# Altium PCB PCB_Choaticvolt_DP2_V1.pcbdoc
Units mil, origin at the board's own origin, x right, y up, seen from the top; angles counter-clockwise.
Board outline 3255.91 x 2971.14 mil, 2 copper layers (Top Layer, Bottom Layer); 27 components, 42 nets, 120 pads, 50 vias.
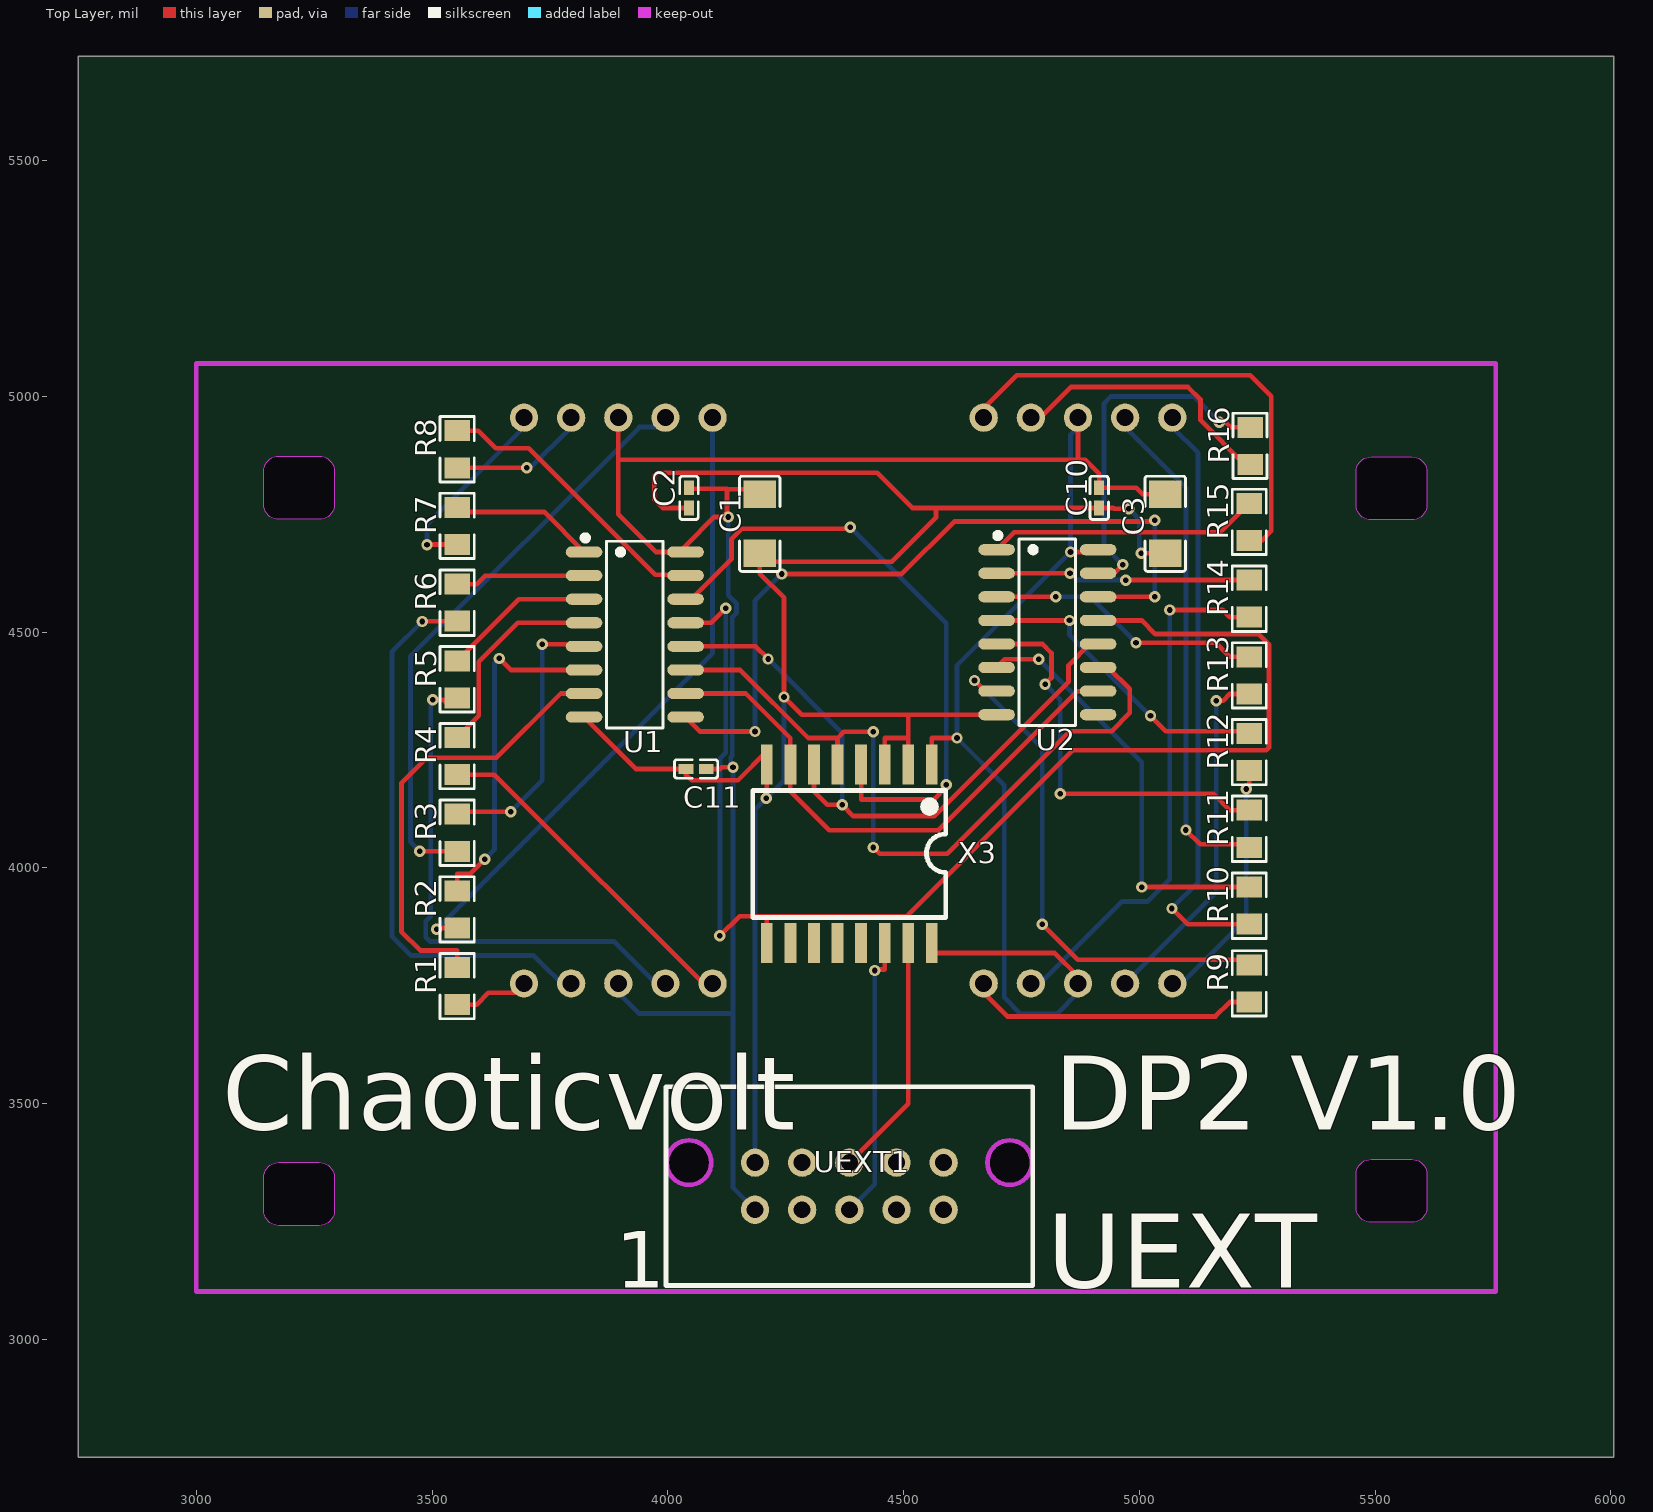
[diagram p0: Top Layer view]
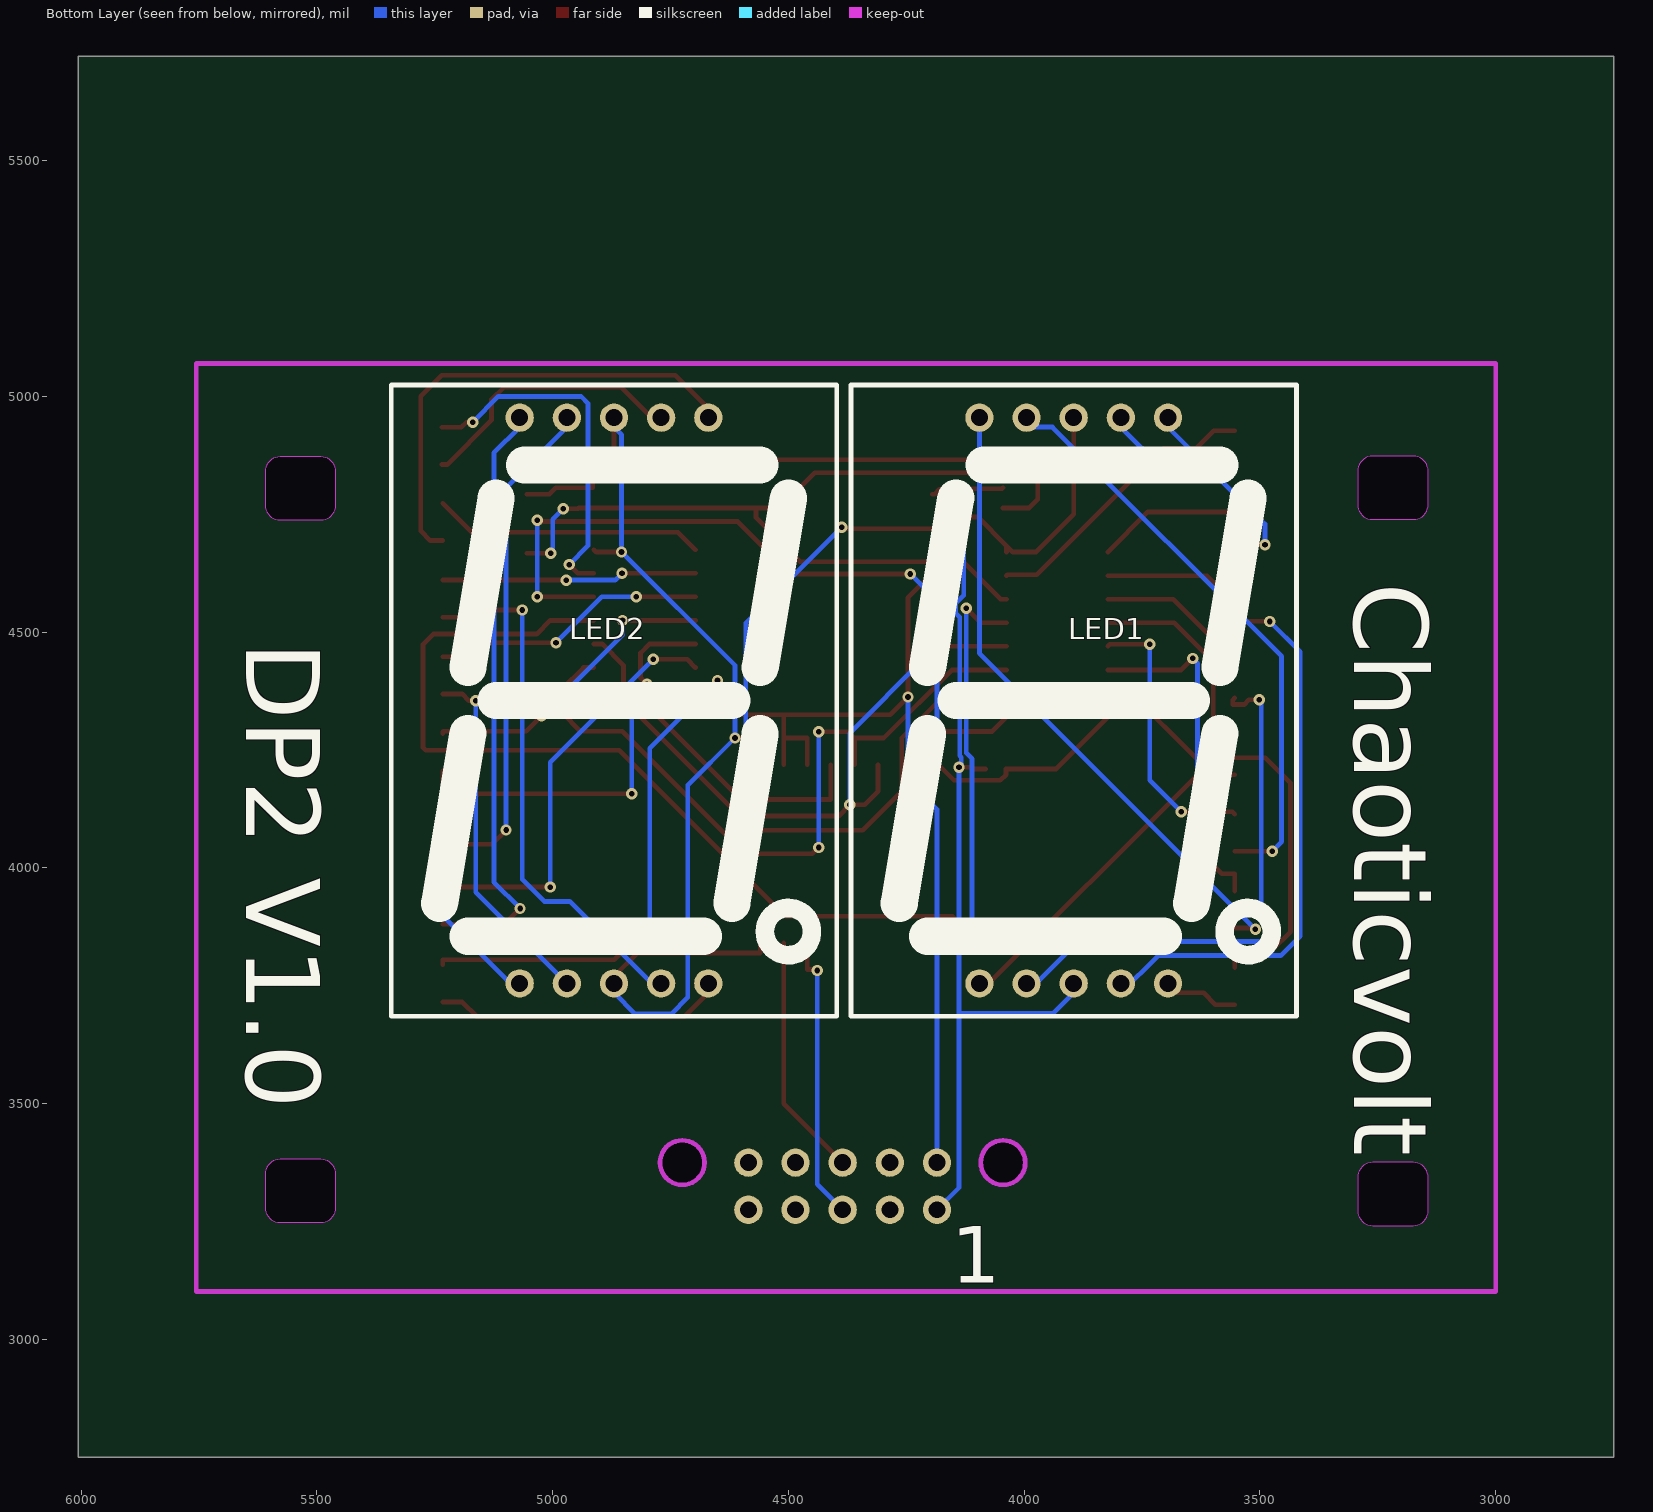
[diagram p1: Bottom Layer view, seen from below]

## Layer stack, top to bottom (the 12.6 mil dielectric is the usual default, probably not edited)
Top Layer: signal copper (thickness not stored)
Dielectric: dielectric 12.6, FR-4, Dk 4.8
Bottom Layer: signal copper (thickness not stored)

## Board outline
6005.91,2750 2750,2750 2750,5721.14 6005.91,5721.14
cut-out: 3174.61,4873.15 3261.22,4873.15 cw(c3261.22,4841.65) 3292.72,4841.65 3292.72,4770.79 cw(c3261.22,4770.79) 3261.22,4739.29 3174.61,4739.29 cw(c3174.61,4770.79) 3143.11,4770.79 3143.11,4841.65 cw(c3174.61,4841.65)
cut-out: 3174.61,3375.28 3261.22,3375.28 cw(c3261.22,3343.78) 3292.72,3343.78 3292.72,3272.91 cw(c3261.22,3272.91) 3261.22,3241.42 3174.61,3241.42 cw(c3174.61,3272.91) 3143.11,3272.91 3143.11,3343.78 cw(c3174.61,3343.78)
cut-out: 5491.69,3381.93 5578.31,3381.93 cw(c5578.31,3350.43) 5609.8,3350.43 5609.8,3279.57 cw(c5578.31,3279.57) 5578.31,3248.07 5491.69,3248.07 cw(c5491.69,3279.57) 5460.2,3279.57 5460.2,3350.43 cw(c5491.69,3350.43)
cut-out: 5491.69,4871.93 5578.31,4871.93 cw(c5578.31,4840.43) 5609.8,4840.43 5609.8,4769.57 cw(c5578.31,4769.57) 5578.31,4738.07 5491.69,4738.07 cw(c5491.69,4769.57) 5460.2,4769.57 5460.2,4840.43 cw(c5491.69,4840.43)

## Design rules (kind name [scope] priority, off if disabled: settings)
Clearance copperThickness1oz [All] p1: gap=7 ignorepadtopadclearanceinfootprint=FALSE except(4: Track-Track; 6: Track-SMDPad SMDPad-SMDPad Track-THPad SMDPad-THPad THPad-THPad Track-Via SMDPad-Via THPad-Via Via-Via SMDPad-Fill THPad-Fill Via-Fill Fill-Fill Track-Region SMDPad-Region THPad-Region Via-Region Region-Region Track-Poly SMDPad-Poly THPad-Poly Via-Poly Fill-Poly Region-Poly Poly-Poly Track-Text SMDPad-Text THPad-Text Via-Text Fill-Text Region-Text Poly-Text Text-Text; 6.9: Track-Hole SMDPad-Hole THPad-Hole Via-Hole Fill-Hole Region-Hole Poly-Hole Text-Hole Sheet-Hole; 11.8: Track-Fill Fill-Region Track-Sheet SMDPad-Sheet THPad-Sheet Via-Sheet Fill-Sheet Region-Sheet Poly-Sheet Text-Sheet)
Clearance copperThickness2oz [All] p1: gap=7 ignorepadtopadclearanceinfootprint=FALSE except(6: Track-SMDPad SMDPad-SMDPad Track-THPad SMDPad-THPad THPad-THPad Track-Via SMDPad-Via THPad-Via Via-Via SMDPad-Fill THPad-Fill Via-Fill Fill-Fill Track-Region SMDPad-Region THPad-Region Via-Region Region-Region Track-Poly SMDPad-Poly THPad-Poly Via-Poly Fill-Poly Region-Poly Poly-Poly Track-Text SMDPad-Text THPad-Text Via-Text Fill-Text Region-Text Poly-Text Text-Text; 6.9: Track-Hole SMDPad-Hole THPad-Hole Via-Hole Fill-Hole Region-Hole Poly-Hole Text-Hole Sheet-Hole; 8: Track-Track; 11.8: Track-Fill Fill-Region Track-Sheet SMDPad-Sheet THPad-Sheet Via-Sheet Fill-Sheet Region-Sheet Poly-Sheet Text-Sheet)
DiffPairsRouting differentialPair [All] p1: maxuncoupledlength=10 maxlimit=5.9843 mostfreqgap=5.9843 toplayer_minwidth=5 toplayer_prefwidth=10 toplayer_maxwidth=100 bottomlayer_minwidth=5 bottomlayer_prefwidth=10 bottomlayer_maxwidth=100
PasteMaskExpansion pasteMaskExpansion [All] p1:
PlaneConnect innerPlane [All] p1: planeconnectstyle=Relief reliefexpansion=20 reliefentries=4 reliefconductorwidth=10 reliefairgap=10
PolygonConnect copperRegion [All] p1: connectstyle=Relief reliefentries=4 reliefconductorwidth=10 polygonreliefangle="90 Angle" airgapwidth=10
PolygonConnect CV-CopperRule01 [All] p1: connectstyle=Relief reliefentries=4 reliefconductorwidth=10 polygonreliefangle="45 Angle" airgapwidth=10
RoutingVias viaSize [All] p1: viastyle="Through Hole" holewidth=12.0078 minholewidth=11.811 maxholewidth=248.0314 width=24.0158 minwidth=19.685 maxwidth=393.7008
SolderMaskExpansion solderMaskExpansion [All] p1: useseparateexpansions=TRUE expansion=2.0079 expansionbottom=2.0079
Width copperThickness1oz [All] p1: maxlimit=100 minlimit=5 preferedwidth=10
Width copperThickness2oz [All] p1: maxlimit=100 minlimit=8 preferedwidth=10

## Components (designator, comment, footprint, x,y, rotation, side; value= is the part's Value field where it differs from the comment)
C1 "CL31A476MPHNNNE" C1206 4195,4730 r270 top
C2 "CL05B104KO5NNNC" C0402 4045,4784.92 r270 top
C3 "CL31A476MPHNNNE" C1206 5055,4730 r270 top
C10 "CL05B104KO5NNNC" C0402 4915,4784.92 r270 top
C11 "CL05B104KO5NNNC" C0402 4060,4210 r0 top
LED1 "SM411006N/15" LED-SEG-TH_10P-L24.0-W34.0-P2.54-S30.48-BL 3895,4355 r180 bottom
LED2 "SM411006N/15" LED-SEG-TH_10P-L24.0-W34.0-P2.54-S30.48-BL 4870,4355 r180 bottom
R1 "0805W8F1200T5E" R0805 3553.23,3749.29 r90 top
R2 "0805W8F1200T5E" R0805 3553.23,3911.97 r90 top
R3 "0805W8F1200T5E" R0805 3553.23,4074.64 r90 top
R4 "0805W8F1200T5E" R0805 3553.23,4237.31 r90 top
R5 "0805W8F1200T5E" R0805 3553.23,4399.98 r90 top
R6 "0805W8F1200T5E" R0805 3553.23,4562.65 r90 top
R7 "0805W8F1200T5E" R0805 3553.23,4725.33 r90 top
R8 "0805W8F1200T5E" R0805 3553.23,4888 r90 top
R9 "0805W8F1200T5E" R0805 5233.29,3755 r90 top
R10 "0805W8F1200T5E" R0805 5233.29,3920 r90 top
R11 "0805W8F1200T5E" R0805 5233.29,4083.1 r90 top
R12 "0805W8F1200T5E" R0805 5233.29,4245.77 r90 top
R13 "0805W8F1200T5E" R0805 5233.29,4408.44 r90 top
R14 "0805W8F1200T5E" R0805 5233.29,4571.11 r90 top
R15 "0805W8F1200T5E" R0805 5233.29,4733.79 r90 top
R16 "0805W8F1200T5E" R0805 5235,4895 r90 top
U1 "74HC595D,118" SOIC-16_L9.9-W3.9-P1.27-LS6.0-BL 3930,4495 r270 top
U2 "74HC595D,118" SOIC-16_L9.9-W3.9-P1.27-LS6.0-BL 4805,4500 r270 top
UEXT1 "15477610" IDC-TH_15477610 4385,3325 r0 top
X3 "PCF8574T/TR" SO-16_L10.3-W7.5-P1.27-LS10.3-BL 4385,4030 r180 top

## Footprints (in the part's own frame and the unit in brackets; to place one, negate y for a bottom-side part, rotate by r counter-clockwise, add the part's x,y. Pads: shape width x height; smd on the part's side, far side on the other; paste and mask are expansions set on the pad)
C0402 [mm]
  rect 0.79x0.54 smd: 1(-0.545,0) 2(0.545,0)
  silkscreen extent -1.17,-0.5 1.17,0.5
C1206 [mm]
  rect 1.485x1.728 smd: 1(-1.593,0) 2(1.593,0)
  silkscreen extent -2.56,-1.09 2.56,1.09
IDC-TH_15477610 [mil]
  round 60 hole 36: 1(-200,-50) 2(-200,50) 3(-100,-50) 4(-100,50) 5(0,-50) 6(0,50) 7(100,-50) 8(100,50) 9(200,-50) 10(200,50)
  Multi-Layer board cut-out: -292.92,50 -299.39,73.44 -316.66,90.55 -340.16,96.81 -363.65,90.55 -380.93,73.44 -387.4,50 -387.4,50 -380.93,26.56 -363.65,9.45 -340.16,3.19 -316.66,9.45 -299.39,26.56 -292.92,50
  Multi-Layer board cut-out: 387.4,50 380.93,73.44 363.66,90.55 340.16,96.81 316.67,90.55 299.39,73.44 292.92,50 292.92,50 299.39,26.56 316.67,9.45 340.16,3.19 363.66,9.45 380.93,26.56 387.4,50
  Multi-Layer keep-out circle w10: c-340.16,50 r47.24
  Multi-Layer keep-out circle w10: c340.16,50 r47.24
  silkscreen extent -389,-211 389,211
LED-SEG-TH_10P-L24.0-W34.0-P2.54-S30.48-BL [mil]
  round 60 hole 36: 1(-200,-600) 2(-100,-600) 3(0,-600) 4(100,-600) 5(200,-600) 6(200,600) 7(100,600) 8(0,600) 9(-100,600) 10(-200,600)
  silkscreen extent -472,-669 472,669
R0805 [mm]
  rect 1.133x1.377 smd: 1(-1,0) 2(1,0)
  silkscreen extent -1.76,-0.92 1.76,0.92
SO-16_L10.3-W7.5-P1.27-LS10.3-BL [mm]
  rect 0.635x2.16 smd: 1(-4.445,-4.8) 2(-3.175,-4.8) 3(-1.905,-4.8) 4(-0.635,-4.8) 5(0.635,-4.8) 6(1.905,-4.8) 7(3.175,-4.8) 8(4.445,-4.8) 9(4.445,4.8) 10(3.175,4.8) 11(1.905,4.8) 12(0.635,4.8) 13(-0.635,4.8) 14(-1.905,4.8) 15(-3.175,4.8) 16(-4.445,4.8)
  silkscreen extent -5.19,-3.41 5.21,3.43
SOIC-16_L9.9-W3.9-P1.27-LS6.0-BL [mil]
  oval 23.7x77.6 smd: 1(-175,-107.7) 2(-125,-107.7) 3(-75,-107.7) 4(-25,-107.7) 5(25,-107.7) 6(75,-107.7) 7(125,-107.7) 8(175,-107.7) 9(175,107.7) 10(125,107.7) 11(75,107.7) 12(25,107.7) 13(-25,107.7) 14(-75,107.7) 15(-125,107.7) 16(-175,107.7)
  silkscreen extent -211,-111 198,60

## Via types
v1: diameter 24, hole 12, Top Layer to Bottom Layer, 50 vias

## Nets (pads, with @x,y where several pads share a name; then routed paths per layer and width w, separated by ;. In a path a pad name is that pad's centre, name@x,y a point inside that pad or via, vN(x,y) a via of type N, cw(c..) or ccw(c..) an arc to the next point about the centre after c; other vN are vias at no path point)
$1N2392: R1.2 U1.7 | length 952.1
  Top Layer w10: R1.2 3553.2,3825.1 3474.97,3825.1 3435,3864.96 3435,4180 3488.8,4233.8 3636.5,4233.8 3772.7,4370 U1.7
$1N2394: R4.2 U1.4 | length 436.9
  Top Layer w10: R4.2 3599,4322.5 3599,4436.9 3682,4520 U1.4
$1N2395: R6.2 U1.2 | length 276.6
  Top Layer w10: R6.2 3594.4,4602 3612.4,4620 U1.2
$1N2396: R7.2 U1.1 | length 314
  Top Layer w10: R7.2 3553.2,4755 3737.44,4755 U1.1
$1N2397: R2.2 U1.6 | length 736.5
  Top Layer w10: R2.2 3553.2,3987.7 3581.1,3987.7 v1(3611.7,4018.3) ; v1(3642.2,4444.4) 3666.6,4420 U1.6
  Bottom Layer w10: v1(3611.7,4018.3) 3632.2,4038.8 3632.2,4434.4 v1(3642.2,4444.4)
$1N2398: R5.2 U1.3 | length 329.4
  Top Layer w10: R5.2 3553.2,4450 3563.8,4450 3683.8,4570 U1.3
$1N2399: R3.2 U1.5 | length 589.3
  Top Layer w10: R3.2 3558.2,4119 v1(3667,4119) ; v1(3733.8,4474.4) 3818,4474.4 U1.5
  Bottom Layer w10: v1(3667,4119) 3733.8,4185.8 v1(3733.8,4474.4)
$1N2400: R8.2 U1.15 | length 611.8
  Top Layer w10: R8.2 3597.6,4927.4 3635,4890 3705,4890 3973.3,4621.7 4036,4621.7 U1.15
$1N2411: R9.2 U2.7 | length 1113.8
  Top Layer w10: v1(4650.5,4397.7) 4673.2,4375 U2.7 ; v1(4794.1,3880.8) 4869.9,3805 5233.3,3805 R9.2
  Bottom Layer w10: v1(4650.5,4397.7) 4794.1,4254.1 v1(4794.1,3880.8)
$1N2412: R12.2 U2.4 | length 655.5
  Top Layer w10: U2.4 v1(4851.9,4525) ; v1(5023.7,4322.6) 5056.3,4290 5232.2,4290 5233.3,4288.9 R12.2
  Bottom Layer w10: v1(4851.9,4525) 4851.9,4494.4 v1(5023.7,4322.6)
$1N2413: R14.2 U2.2 | length 542
  Top Layer w10: U2.2 v1(4852.9,4625) ; v1(4971.5,4610.5) R14.2
  Bottom Layer w10: v1(4852.9,4625) 4867.4,4610.5 v1(4971.5,4610.5)
$1N2414: R15.2 U2.1 | length 576.7
  Top Layer w10: U2.1 4734.4,4712.1 5172.2,4712.1 R15.2
$1N2415: R10.2 U2.6 | length 898.6
  Top Layer w10: U2.6 4715.1,4442.8 v1(4786.6,4442.8) ; v1(5005.4,3959.4) R10.2
  Bottom Layer w10: v1(4786.6,4442.8) 5005.4,4224.1 v1(5005.4,3959.4)
$1N2416: R13.2 U2.3 | length 588.7
  Top Layer w10: U2.3 v1(4822.6,4575) ; v1(4993.1,4477.7) 5162.3,4477.7 5192.2,4447.8 R13.2
  Bottom Layer w10: v1(4822.6,4575) 4895.8,4575 v1(4993.1,4477.7)
$1N2417: R11.2 U2.5 | length 857.2
  Top Layer w10: U2.5 4794.6,4475 4813.7,4455.9 4813.7,4402.9 v1(4800.2,4389.4) ; v1(4832.4,4157.3) 5157.4,4157.3 5192.2,4122.5 R11.2
  Bottom Layer w10: v1(4800.2,4389.4) 4832.4,4357.2 v1(4832.4,4157.3)
$1N2418: R16.2 U2.15 | length 761.4
  Top Layer w10: U2.15 4946.7,4625 v1(4965.1,4643.4) ; v1(5169.9,4945.3) 5182.9,4945.3 5193.9,4934.4 R16.2
  Bottom Layer w10: v1(4965.1,4643.4) 4925.2,4683.3 4925.2,4985.2 4940,5000 5115.2,5000 v1(5169.9,4945.3)
$1N2428: U1.9 U2.14 | length 1638
  Top Layer w10: U1.9 4068.2,4289.5 v1(4184.9,4289.5) ; v1(4241.9,4623.6) 4496.3,4623.6 4607.3,4734.6 5029.6,4734.6 v1(5032.6,4737.6) ; U2.14 v1(5032.6,4575)
  Bottom Layer w10: v1(4184.9,4289.5) 4184.9,4566.6 v1(4241.9,4623.6) ; v1(5032.6,4575) v1(5032.6,4737.6)
$1N2430: U1.11 U2.11 X3.5 | length 1575.8
  Top Layer w10: U1.11 4153.1,4420 4297.6,4275.6 4360,4275.6 ; X3.5 4360,4275.6 ; v1(4435.9,4043.4) 4449.3,4030 4592.49,4030 4852.6,4290 4941.3,4290 4980,4328.7 4980,4379.6 4934.6,4425 U2.11 ; v1(4435.9,4288.8) 4373.2,4288.8 4360,4275.6
  Bottom Layer w10: v1(4435.9,4043.4) v1(4435.9,4288.8)
$1N2434: U1.12 U2.12 X3.6 | length 1413.2
  Top Layer w10: U1.12 4185.9,4470 v1(4212.7,4443.2) ; X3.6 4310,4162.5 4338.6,4133.8 v1(4370,4133.8) 4393.8,4110 4565,4110 4850,4395 4850,4429.8 4895.2,4475 U2.12
  Bottom Layer w10: v1(4212.7,4443.2) 4370,4285.8 v1(4370,4133.8)
$1N2437: U1.13 U2.13 X3.9 | length 2786.4
  Top Layer w10: U1.13 4092.2,4520 v1(4122.8,4550.6) ; v1(4110.5,3855.9) 4152.2,3897.6 4210,3897.6 ; X3.9 4210,3897.6 ; U2.13 5005,4525 5033.9,4496.1 5253.1,4496.1 5275,4474.3 5275,4255.2 5269.3,4249.5 4858.8,4249.5 4506.8,3897.6 4210,3897.6
  Bottom Layer w10: v1(4110.5,3855.9) 4110.5,4231.8 4122.8,4244 v1(4122.8,4550.6)
$1N3740: U1.14 X3.4 | length 1338.3
  Top Layer w10: U1.14 4050.2,4570 4135,4654.88 4135,4697 4157.2,4719.2 4384,4719.2 v1(4387.3,4722.5) ; X3.4 4410,4145 4563.7,4145 4590.9,4172.2 v1(4590.9,4176.3)
  Bottom Layer w10: v1(4387.3,4722.5) 4590.42,4519.38 4590.42,4176.78 v1(4590.9,4176.3)
$1N3774: U1.10 U2.10 X3.7 | length 1183.6
  Top Layer w10: U1.10 4165.6,4370 4260,4275.6 X3.7 4260,4162.5 4342.34,4080 4573.7,4080 4868.7,4375 U2.10
$1N3917: UEXT1.5 X3.14 | length 608.3
  Top Layer w10: v1(4438.9,3782.5) 4440.8,3784.5 4460,3784.5 X3.14
  Bottom Layer w10: UEXT1.5 4438.9,3328.9 v1(4438.9,3782.5)
$1N3924: UEXT1.6 X3.15 | length 517.8
  Top Layer w10: UEXT1.6 4510,3500 X3.15
$1N26641: LED1.6 R7.1 | length 398.2
  Top Layer w10: v1(3489.4,4685.8) 3511.9,4685.8 3512.1,4686 R7.1
  Bottom Layer w10: v1(3489.4,4685.8) 3489.4,4729.4 LED1.6@3695,4935
$1N26647: LED1.7 R8.1 | length 277.6
  Top Layer w10: R8.1 v1(3700.7,4848.6)
  Bottom Layer w10: v1(3700.7,4848.6) 3708.6,4848.6 LED1.7@3795,4935
$1N26729: LED1.2 R5.1 | length 1143.4
  Top Layer w10: v1(3501.5,4356.5) 3523.66,4356.5 3533.66,4346.5 3557.63,4346.5 3557.63,4356.16 R5.1
  Bottom Layer w10: v1(3501.5,4356.5) 3497.18,4352.18 3497.18,3897.55 3486.62,3887.01 3486.62,3852.5 3494.92,3844.2 3885.8,3844.2 LED1.2@3995,3735
$1N26736: LED1.1 R4.1 | length 733.5
  Top Layer w10: R4.1 3632.1,4197.9 LED1.1@4095,3735
$1N26743: LED1.9 R3.1 | length 1243.2
  Top Layer w10: v1(3474.2,4035.3) R3.1
  Bottom Layer w10: v1(3474.2,4035.3) 3454.2,4055.3 3454.2,4449.2 3940,4935 LED1.9@3995,4935
$1N26751: LED1.10 R2.1 | length 1351.8
  Top Layer w10: v1(3509.6,3870.2) 3512.1,3872.6 R2.1
  Bottom Layer w10: v1(3509.6,3870.2) 4095,4455.6 LED1.10@4095,4935
$1N26868: LED2.6 R15.1 | length 1038.1
  Top Layer w10: LED2.6@4670,4935 4670,4975 4740.2,5045.2 5235.2,5045.2 5279.8,5000.7 5279.8,4714.8 5259.41,4694.41 R15.1
$1N26872: LED2.7 R16.1 | length 594
  Top Layer w10: LED2.7@4770,4935 4855,5020 5103.35,5020 5130,4993.35 5130,4949.5 5223.9,4855.6 R16.1
$1N26877: LED2.2 R13.1 | length 775.8
  Top Layer w10: v1(5163.3,4354.9) 5178,4354.9 5192.2,4369.1 R13.1
  Bottom Layer w10: LED2.2@4970,3735 LED2.2 5163.3,3948.3 v1(5163.3,4354.9)
$1N26881: LED2.1 R12.1 | length 541.1
  Top Layer w10: v1(5226.9,4167.3) 5229.7,4170.1 5233.3,4170.1 R12.1
  Bottom Layer w10: LED2.1@5070,3735 5226.9,3891.9 v1(5226.9,4167.3)
$1N26885: LED2.9 R11.1 | length 1061.3
  Top Layer w10: v1(5098.9,4080.4) 5129.3,4050 5233.3,4050 R11.1
  Bottom Layer w10: LED2.9@4970,4935 5098.9,4806.1 v1(5098.9,4080.4)
$1N26891: LED2.10 R10.1 | length 1244.5
  Top Layer w10: v1(5069.2,3914) 5102.6,3880.6 R10.1
  Bottom Layer w10: v1(5069.2,3914) 5124.6,3969.4 5124.6,4880.4 LED2.10@5070,4935
$1N27647: LED1.4 R6.1 | length 1198.4
  Top Layer w10: v1(3478.9,4522.7) 3479.5,4523.3 R6.1
  Bottom Layer w10: v1(3478.9,4522.7) 3415,4458.8 3415,3855 3455.8,3814.2 3715.8,3814.2 LED1.4@3795,3735
$1N27662: LED1.5 R1.1 | length 152.2
  Top Layer w10: R1.1 3594.4,3709.9 3619.5,3735 LED1.5@3695,3735
$1N27688: LED2.4 R14.1 | length 1140.9
  Top Layer w10: v1(5064.4,4547.2) 5176.7,4547.2 5192.2,4531.7 R14.1
  Bottom Layer w10: LED2.4@4770,3735 4964,3929 5017.7,3929 5064.4,3975.7 v1(5064.4,4547.2)
$1N27703: LED2.5 R9.1 | length 596.7
  Top Layer w10: LED2.5@4670,3735 4720,3685 5161.6,3685 5192.2,3715.6 R9.1
GND: 
VCC: C1.1 C2.1 C3.1 C10.1 C11.2 LED1.3 LED1.8 LED2.3 LED2.8 U1.16 U2.16 UEXT1.1 X3.1 X3.16 | length 5918.4
  Top Layer w10: LED1.8@3895,4935 3895,4865.7 ; U1.16 4037.7,4683.4 ; C2.1 4046.4,4805 4125.55,4803.64 ; C11.2 4111.2,4210 4114.4,4213.3 v1(4138.3,4213.3) ; v1(4127.98,4744.5) 4115.2,4744.5 ; C1.1 4190,4792.7 4180,4802.7 4125.55,4803.64 ; X3.16 4560,3819.5 4820.6,3819.5 4870.04,3769.96 LED2.3@4870,3735 ; X3.1 4560,4275.6 v1(4613.4,4275.6) ; v1(4854,4670) 4907.7,4670 U2.16 ; LED2.8@4870,4935 4870,4865.7 ; C3.1 5007,4792.7 4993.3,4806.4 C10.1 4915,4836.1 4885.4,4865.7 4870,4865.7 ; 3895,4865.7 4870,4865.7 ; 3895,4865.7 3895,4750 3975,4670 4024.3,4670 4037.7,4683.4 ; 4037.7,4683.4 4098.7,4744.5 4115.2,4744.5 ; 4115.2,4744.5 4125.55,4754.85 4125.55,4803.64
  Bottom Layer w10: LED1.3@3895,3735 3938.7,3691.3 4138.3,3691.3 ; v1(4127.98,4744.5) 4127.98,4577.92 4145.78,4560.12 4145.78,4541.08 4136.82,4532.11 4136.82,4238.19 4133.6,4234.97 4133.6,4218 v1(4138.3,4213.3) 4138.3,3691.3 ; UEXT1.1 4138.3,3321.7 4138.3,3691.3 ; LED2.3@4870,3735 4825,3690 4748.6,3690 4713.3,3725.4 4713.3,4175.7 v1(4613.4,4275.6) 4613.4,4429.4 v1(4854,4670) 4854,4919 LED2.8@4870,4935
pads on no net: C1.2 C2.2 C3.2 C10.2 C11.1 U1.8 U2.8 U2.9 UEXT1.2 UEXT1.3 UEXT1.4 UEXT1.7 UEXT1.8 UEXT1.9 UEXT1.10 X3.2 X3.3 X3.8 X3.10 X3.11 X3.12 X3.13
copper on no net: | length 4357.5
  Top Layer w10: 3822.3,4320 3932.3,4210 4038.5,4210 4038.5,4198.1 4050.5,4186.1 4148.9,4186.1 4210,4247.3 4210,4219 4210,4149 v1(4208.6,4147.6) ; 4045,4763.5 3989.1,4763.5 3971.1,4781.5 3971.1,4832.3 3977.2,4838.4 4443.9,4838.4 4518.8,4763.5 4568.8,4763.5 ; 4195,4667.3 4195,4645.7 ; 4460,4219 4460,4275.6 4510,4275.6 ; 4510,4219 4510,4275.6 ; 4697.3,4325 4510,4325 ; v1(4977.7,4761.9) 4946.3,4761.9 4944.7,4763.5 4915,4763.5 4568.8,4763.5 ; v1(5004.3,4667.3) 5055,4667.3 ; 4195,4645.7 4199.1,4649.7 4475.3,4649.7 4568.8,4743.2 4568.8,4763.5 ; 4195,4645.7 4195,4624.1 4246.5,4572.6 v1(4246.5,4362.4) 4283.9,4325 4510,4325 ; 4510,4275.6 4510,4325
  Bottom Layer w10: 4185,3375 4185,4124 v1(4208.6,4147.6) 4246.5,4185.5 v1(4246.5,4362.4) ; v1(4977.7,4761.9) 5000,4739.6 5000,4671.6 v1(5004.3,4667.3)

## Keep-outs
Board Outline Layer:
  lines w10: 3000,3101.5 5755.91,3101.5 5755.91,5070 3000,5070 3000,3101.5
Multi-Layer:
  region: 3174.61,4873.15 3261.22,4873.15 cw(c3261.22,4841.65) 3292.72,4841.65 3292.72,4770.79 cw(c3261.22,4770.79) 3261.22,4739.29 3174.61,4739.29 cw(c3174.61,4770.79) 3143.11,4770.79 3143.11,4841.65 cw(c3174.61,4841.65)
  region: 3174.61,3375.28 3261.22,3375.28 cw(c3261.22,3343.78) 3292.72,3343.78 3292.72,3272.91 cw(c3261.22,3272.91) 3261.22,3241.42 3174.61,3241.42 cw(c3174.61,3272.91) 3143.11,3272.91 3143.11,3343.78 cw(c3174.61,3343.78)
  region: 5491.69,3381.93 5578.31,3381.93 cw(c5578.31,3350.43) 5609.8,3350.43 5609.8,3279.57 cw(c5578.31,3279.57) 5578.31,3248.07 5491.69,3248.07 cw(c5491.69,3279.57) 5460.2,3279.57 5460.2,3350.43 cw(c5491.69,3350.43)
  region: 5491.69,4871.93 5578.31,4871.93 cw(c5578.31,4840.43) 5609.8,4840.43 5609.8,4769.57 cw(c5578.31,4769.57) 5578.31,4738.07 5491.69,4738.07 cw(c5491.69,4769.57) 5460.2,4769.57 5460.2,4840.43 cw(c5491.69,4840.43)

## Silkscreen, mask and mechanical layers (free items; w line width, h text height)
Top Silkscreen Layer:
  text "Chaoticvolt" at 3055,3445 h157.48
  text "DP2 V1.0" at 4820,3445 h157.48
  text "1" at 3890,3110 h120
  text "UEXT" at 4805,3110 h157.48
Bottom Silkscreen Layer:
  text "Chaoticvolt" at 3300,4605 h157.48 r90
  text "DP2 V1.0" at 5650,4480 h157.48 r90
  text "1" at 4155,3120 h120
Mechanical Layer:
  lines w1: 3143.11,3272.91 ccw(c3174.61,3272.91) 3174.61,3241.42 3261.22,3241.42 ccw(c3261.22,3272.91) 3292.72,3272.91 3292.72,3343.78 ccw(c3261.22,3343.78) 3261.22,3375.28 3174.61,3375.28 ccw(c3174.61,3343.78) 3143.11,3343.78 3143.11,3272.91 ; 3143.11,4770.79 ccw(c3174.61,4770.79) 3174.61,4739.29 3261.22,4739.29 ccw(c3261.22,4770.79) 3292.72,4770.79 3292.72,4841.65 ccw(c3261.22,4841.65) 3261.22,4873.15 3174.61,4873.15 ccw(c3174.61,4841.65) 3143.11,4841.65 3143.11,4770.79 ; 5460.2,3279.57 ccw(c5491.69,3279.57) 5491.69,3248.07 5578.31,3248.07 ccw(c5578.31,3279.57) 5609.8,3279.57 5609.8,3350.43 ccw(c5578.31,3350.43) 5578.31,3381.93 5491.69,3381.93 ccw(c5491.69,3350.43) 5460.2,3350.43 5460.2,3279.57 ; 5460.2,4769.57 ccw(c5491.69,4769.57) 5491.69,4738.07 5578.31,4738.07 ccw(c5578.31,4769.57) 5609.8,4769.57 5609.8,4840.43 ccw(c5578.31,4840.43) 5578.31,4871.93 5491.69,4871.93 ccw(c5491.69,4840.43) 5460.2,4840.43 5460.2,4769.57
